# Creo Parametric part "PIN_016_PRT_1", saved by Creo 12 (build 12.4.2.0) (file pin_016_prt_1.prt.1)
Units: Custom; MM, KILOGRAM, SECS

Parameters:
  PTC_WM_ITERATION = "0"
  PTC_WM_VERSION = "-.0"
  PTC_WM_LIFECYCLE_STATE = "In Work"
  PTC_WM_LIFECYCLE = "MO_CADDocument"
  PTC_WM_CREATED_BY = "Maximilian Roepper (Z0017RMS: MO)"
  PTC_WM_CREATED_ON = "18-Sep-26 11:36:42 AM"
  PTC_WM_MODIFIED_BY = "Maximilian Roepper (Z0017RMS: MO)"
  PTC_WM_MODIFIED_ON = "18-Sep-26 11:36:46 AM"
  PDMLINKNUMBER = "PDM000071454979"
  PTC_WM_NAME = "pin_016_prt_1.prt"
  PTC_WM_NUMBER = "PDM000071454979"

Other parameters: WEIGHT, WEIGHT_FACTOR, WEIGHT_ADD, _MASS_TEMP, _DIFF_TEMP, MC_ERRORS, SUPPLIER

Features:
  1. coordinate system
  2. datum plane "PRT_YZ"
  3. datum plane "PRT_XY"
  4. datum plane "PRT_XZ"
  5. coordinate system
  6. datum axis
  7. datum axis
  8. datum axis
  9. coordinate system
  10. imported feature
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
Other named items: PRT, SIEMENS_MO, DRW_VIEW_ORG, PRT_X, PRT_Y, PRT_Z, CS0, ROUGH_GROB

Layers: 00_STD_CSYS-KSYS, 01_STD_PLANES-EBENEN, 02_STD_AXES-ACHSEN, 03_STD_CSYS-KSYS, 24_IMPORT_FEAT-IMPORT_KE

Surfaces: 9 plane, 1 cylinder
